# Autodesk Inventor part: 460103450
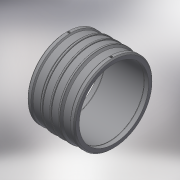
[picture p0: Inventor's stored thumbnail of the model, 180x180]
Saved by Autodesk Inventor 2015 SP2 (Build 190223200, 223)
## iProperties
Created: 2017-06
Part Number: 460103450
Material: Generic
Description: PLASSON LIGHTFIT COUPLER 450
Document SubType Name: Modeling
Designer: KIM
Mass: 12691.5 g
Surface Area: 10606.6 cm^2
Volume: 12691.5 cm^3
Density: 1 g/cm^3
Appearance: Default
Author: KIM
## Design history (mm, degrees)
derived "460103.ipt"
feature "Solid1::460103.ipt"
tag "TaggingFeature1"
body "Solid1"
other parameters: "d14" = 17.6296, "d15" = 155, "d16" = 155, "d19" = 3.52592, "d20" = 168 deg, "d23" = 518, "d24" = 494.7, "d25" = 135 deg, "d26" = 124, "d27" = 135 deg, "d29" = 255, "d35" = 15, "d39" = 0, "d40" = 4, "d41" = 14, "d42" = 0, "d43" = 135 deg, "d44" = 34.1, "d45" = 12.4, "d46" = 12.4, "d47" = 12.4, "d48" = 507.64, "d49" = 518, "d50" = 2.59, "d51" = 6, "d52" = 0, "L_1" = 155, "D_" = 518, "A_" = 255, "d_2" = 12
